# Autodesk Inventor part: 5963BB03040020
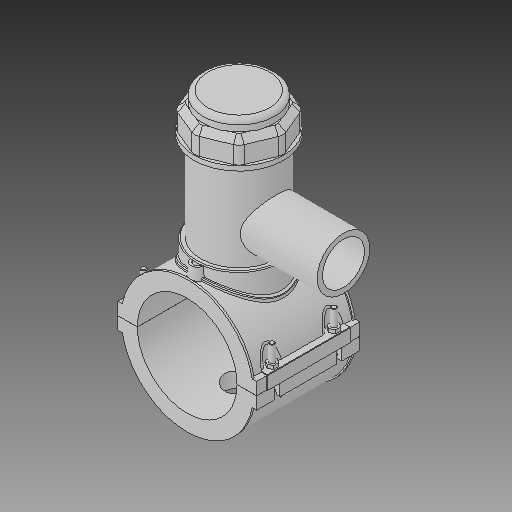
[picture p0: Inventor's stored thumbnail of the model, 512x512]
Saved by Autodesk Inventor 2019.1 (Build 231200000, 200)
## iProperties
Created: 2017-07
Part Number: 5963BB03040020
Material: Generic
Description: PLASSON TAPPING SADDLE 4''IPS x 2''IPS
Document SubType Name: Modeling
Designer: KIM
Mass: 1712.7 g
Surface Area: 2671.49 cm^2
Volume: 1712.7 cm^3
Density: 1 g/cm^3
Appearance: Default
Author: KIM
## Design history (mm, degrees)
derived "5963B.ipt"
feature "Solid1::5963B.ipt"
feature "Solid2::5963B.ipt"
feature "Solid4::5963B.ipt"
feature "Solid5::5963B.ipt"
tag "TaggingFeature1"
body "Solid1"
body "Solid2"
other parameters: "d0" = 114.1, "d2" = 159.004, "d3" = 28.525, "d4" = 118.11, "d5" = 0, "d6" = 0.1, "d8" = 0, "d19" = 6, "d20" = 6, "d21" = 70.866, "d23" = 0, "d24" = 35.433, "d26" = 0, "d29" = 3, "d30" = 38.03333, "d31" = 6, "d32" = 0, "d33" = 0, "d34" = 0.6, "d40" = 77.1316, "d41" = 102.69, "d43" = 0, "d45" = 0, "d47" = 145.031, "d70" = 15, "d72" = 0, "d73" = 6, "d75" = 5, "d76" = 0, "d77" = 5.705, "d78" = 87.05, "d79" = 15, "d80" = 47.244, "d82" = 5 deg, "d84" = 4, "d85" = 14, "d86" = 0, "d87" = 3, "d88" = 0, "d89" = 1, "d90" = 1, "d91" = 94.488, "d92" = 0, "d93" = 0.5, "d94" = 60.05263, "d96" = 151.2966, "d97" = 2.3622, "d98" = 0, "d102" = 1.141, "d120" = 140 deg, "d121" = 24.228, "d122" = 20 deg, "d123" = 296.66, "d124" = 88.998, "d126" = 0, "d143" = 117.523, "d145" = 26.33077, "d149" = 1.7115, "d150" = 28.96385, "d153" = 118.11, "d154" = 0, "d156" = 74.165, "d157" = 160 deg, "d159" = 6.846, "d161" = 1.7115, "d162" = 70.866, "d163" = 0, "d164" = 57.05, "d167" = 11.41, "d168" = 72.3561, "d170" = 3.2805, "d172" = 0, "d173" = 1, "d175" = 57.05, "d176" = 20 deg, "d177" = 7.987, "d178" = 34.23, "d180" = 0, "d183" = 13.692, "d184" = 6.3896, "d185" = 38.38575, "d186" = 38.38575, "d187" = 74.165, "d188" = 10.269, "d189" = 7.987, "d190" = 0, "d191" = 111.2475, "d193" = 6.1236, "d194" = 4.13385, "d195" = 90 deg, "d197" = 0, "d199" = 0, "d200" = 17.115, "d202" = 0, "d203" = 177.038, "d204" = 97.5555, "d205" = 71.883, "d206" = 87.2865, "d207" = 132.7785, "d208" = 138.08964, "d209" = 164.64534, "d210" = 88.3134, "d211" = 102.69, "d212" = 82.152, "d213" = 31.4766, "d216" = 0, "d217" = 11.41, "d218" = 5.705, "d219" = 1.141, "d222" = 114.1, "d224" = 0, "d230" = 6.846, "d233" = 6, "d236" = 79.502, "d237" = 35.433, "d238" = 6.02433, "d240" = 35.433, "d241" = 35.433, "d242" = 35.433, "d243" = 6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
